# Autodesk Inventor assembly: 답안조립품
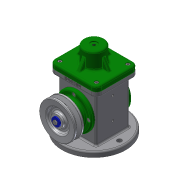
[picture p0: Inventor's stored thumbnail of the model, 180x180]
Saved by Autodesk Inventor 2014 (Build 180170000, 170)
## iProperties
Created: 2018-10
Part Number: 답안조립품
Document SubType Name: Assembly
Designer: 602-14
Author: 602-14
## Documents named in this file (18)
- C:\Users\602-14\Desktop\481008V1001\답안조립품.iam
- C:\Users\602-14\Desktop\481008V1001\본체.ipt
- C:\Users\602-14\Desktop\481008V1001\볼트 M4 x 8.ipt
- C:\Users\602-14\Desktop\481008V1001\볼트 M4 x 10.ipt
- C:\Users\602-14\Desktop\481008V1001\슬라이더.ipt
- C:\Users\602-14\Desktop\481008V1001\앞커버.ipt
- C:\Users\602-14\Desktop\481008V1001\오일 실 17 30 8.ipt
- C:\Users\602-14\Desktop\481008V1001\와셔 4x16.ipt
- C:\Users\602-14\Desktop\481008V1001\클레비스 핀 6 x 22.ipt
- 클레비스 핀 6 x 22.ipt
- C:\Users\602-14\Desktop\481008V1001\키 4 x 4 x 12.ipt
- C:\Users\602-14\Desktop\481008V1001\편심축.ipt
- C:\Users\602-14\Desktop\481008V1001\E-링.ipt
- C:\Users\602-14\Desktop\481008V1001\V-벨트풀리.ipt
- C:\Users\602-14\Desktop\481008V1001\덮개.ipt
- C:\Users\602-14\Desktop\481008V1001\뒤커버.ipt
- C:\Users\602-14\Desktop\481008V1001\링크.ipt
- C:\Users\602-14\Desktop\481008V1001\베어링 17 x 40 x 12.ipt
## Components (2 placed, 2 different names)
1. E-링:1
2. V-벨트풀리:1
